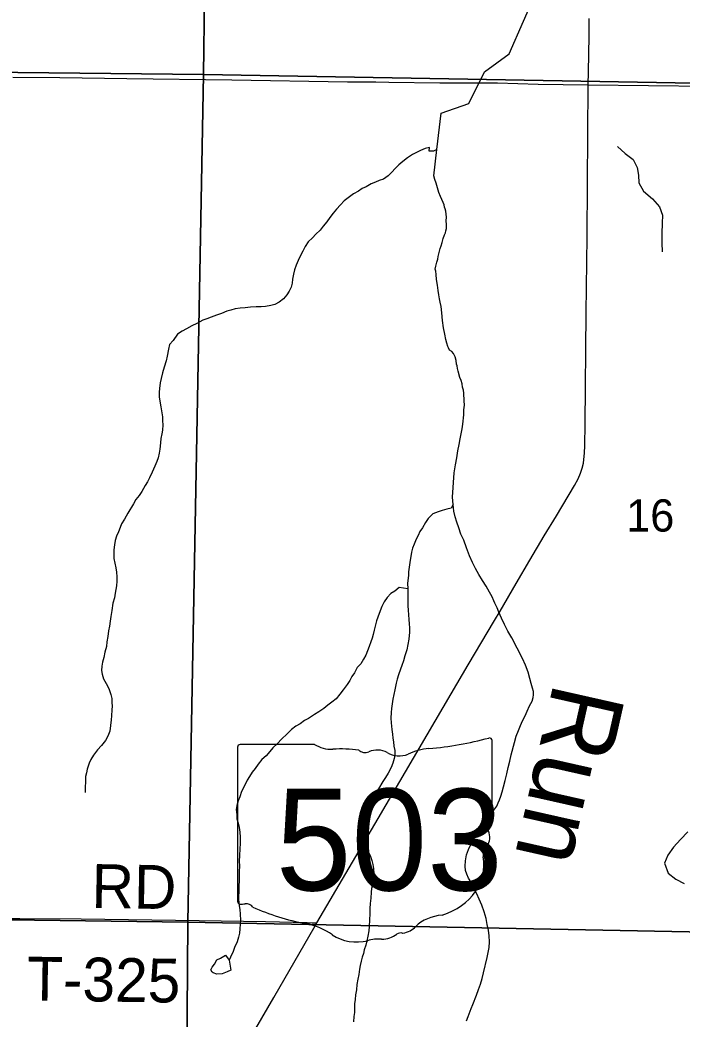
# Model space of a CAD drawing. Extents: x -8.8 to 41.4, y 0 to 34.6.
# Drawn here: x -3.661 to -2.803, y 15.304 to 16.599 of the extents above; entities that cross this region are included whole.
import ezdxf

# ---------------------------------------------------------------- set-up
doc = ezdxf.new("R2010")
doc.units = 0
for name, color, linetype in [('GM_X_City_Street', 7, 'Continuous'), ('GM_X_Corporation', 7, 'Continuous'), ('GM_X_County_Road', 7, 'Continuous'), ('GM_X_Minor_River', 7, 'Continuous'), ('GM_X_Minor_River_Text', 7, 'Continuous'), ('GM_X_Section_Text', 7, 'Continuous'), ('GM_X_State_Route', 7, 'Continuous'), ('GM_X_Township_Road', 7, 'Continuous'), ('GM_X_Township_Text', 7, 'Continuous'), ('GM_X_Unincorporated_Location', 7, 'Continuous')]:
    doc.layers.add(name, color=color, linetype=linetype)

msp = doc.modelspace()

# ---------------------------------------------------------------- linework, layer by layer
at = {"layer": 'GM_X_City_Street'}
for p, q in [((-3.0493, 15.5601), (-3.0493, 15.6648)), ((-3.3789, 15.6564), (-3.3789, 15.4563)), ((-3.2792, 15.6598), (-3.3757, 15.6598)), ((-3.0494, 15.5601), (-3.0493, 15.5601))]:
    msp.add_line(p, q, dxfattribs=at)
for centre, major_axis, start_param, end_param in [((-3.1667, 15.9326), (0.3495, 0), 4.814394, 5.042369), ((-3.053, 15.6652), (0.00367, 0), 6.141152, 7.989035), ((-3.3751, 15.6568), (0.00382, 0), 1.712693, 3.28349), ((-3.2562, 15.683), (0.037, 0), 4.042523, 4.731795), ((-3.2439, 15.5475), (0.133, 0), 1.404758, 1.657858), ((-3.2137, 15.6578), (0.0107, 0), 3.836095, 5.185415), ((-3.198, 15.6347), (0.0222, 0), 0.950623, 2.079405), ((-3.1694, 15.6664), (0.0267, 0), 4.081561, 5.145723), ((-3.1222, 15.5987), (0.0703, 0), 1.699011, 2.107814), ((-3.0533, 15.5597), (0.00393, 0), 5.05454, 6.418171), ((-3.0502, 15.5524), (0.00568, 0), 1.883978, 3.671073), ((-3.0863, 15.5392), (0.0341, 0), 5.934695, 6.695948), ((-3.0362, 15.5163), (0.0248, 0), 2.387724, 3.262537), ((-3.1472, 15.503), (0.0874, 0), 5.101752, 6.440018), ((-3.3751, 15.4558), (0.00385, 0), 3.00124, 4.508301), ((-3.3745, 15.4763), (0.0294, 0), 4.665946, 4.897461), ((-3.3685, 15.4447), (0.0106, 0), 0.519207, 1.627899), ((-3.2347, 15.6245), (0.2524, 0), 4.195997, 4.488961), ((-3.1103, 15.4001), (0.0479, 0), 1.647645, 2.488434), ((-3.3099, 15.3663), (0.079, 0), 0.823519, 1.323587), ((-3.1678, 15.4093), (0.00752, 0), 1.147584, 2.315152), ((-3.171, 15.4369), (0.0282, 0), 4.937069, 5.64225), ((-3.2245, 15.4437), (0.0501, 0), 4.026481, 4.996735), ((-3.1956, 15.3745), (0.0412, 0), 1.495662, 1.94098), ((-3.1919, 15.4287), (0.0267, 0), 4.691044, 5.507374)]:
    msp.add_ellipse(centre, major_axis=major_axis, ratio=0.8, start_param=start_param, end_param=end_param, dxfattribs=at)
at = {"layer": 'GM_X_Corporation'}
for points in [[(-3.4102, 17.5315), (-3.4233, 16.5283), (-4.4254, 16.539), (-4.4134, 17.5464)], [(-2.4162, 17.5144), (-2.421, 16.5107), (-3.4233, 16.5283), (-3.4102, 17.5315)], [(-4.4254, 16.539), (-3.4233, 16.5283), (-3.4436, 15.4293), (-4.4369, 15.4422)], [(-3.4233, 16.5283), (-2.421, 16.5107), (-2.4357, 15.4097), (-3.4436, 15.4293)], [(-4.4369, 15.4422), (-3.4436, 15.4293), (-3.4507, 14.4245), (-4.4383, 14.4395)], [(-3.4436, 15.4293), (-2.4357, 15.4097), (-2.4445, 14.411), (-3.4507, 14.4245)]]:
    msp.add_lwpolyline(points, close=True, dxfattribs=at)
at = {"layer": 'GM_X_County_Road'}
for points in [[(-3.6702, 16.5251), (-3.6094, 16.5244), (-3.5224, 16.5234), (-3.3864, 16.5217), (-3.2367, 16.5191), (-3.2, 16.5187), (-3.1832, 16.5184), (-3.1169, 16.5178), (-3.0424, 16.5174), (-2.9897, 16.516), (-2.9247, 16.5151)], [(-2.9247, 16.5151), (-2.6903, 16.5124), (-2.4218, 16.5093), (-2.1878, 16.5068), (-1.9834, 16.5044), (-1.8743, 16.5027)]]:
    msp.add_lwpolyline(points, dxfattribs=at)
at = {"layer": 'GM_X_Minor_River'}
for points in [[(-3.1207, 16.431), (-3.1153, 16.4782), (-3.0793, 16.4906), (-3.0589, 16.5317), (-3.027, 16.5553), (-2.9899, 16.6404)], [(-3.1359, 16.4324), (-3.1421, 16.4299), (-3.1471, 16.4274), (-3.1525, 16.4245), (-3.1587, 16.4205), (-3.1649, 16.4154), (-3.1699, 16.4113), (-3.184, 16.3969), (-3.1898, 16.3929), (-3.1956, 16.3908), (-3.2005, 16.3886), (-3.2059, 16.3865), (-3.2125, 16.3829), (-3.2175, 16.3808), (-3.2225, 16.3771), (-3.2287, 16.3735), (-3.2356, 16.3687), (-3.2407, 16.3647), (-3.2458, 16.3595), (-3.2509, 16.354), (-3.2552, 16.3488), (-3.2595, 16.3428), (-3.2635, 16.3372), (-3.2682, 16.3317), (-3.2721, 16.3265), (-3.2776, 16.3213), (-3.2819, 16.3165), (-3.2874, 16.3113), (-3.2913, 16.3053), (-3.2945, 16.2993), (-3.2977, 16.293), (-3.3006, 16.2874), (-3.303, 16.2813), (-3.3051, 16.2753), (-3.3064, 16.2697), (-3.3077, 16.2632), (-3.3082, 16.2579), (-3.3095, 16.2527), (-3.3123, 16.2474), (-3.3151, 16.2426), (-3.3194, 16.2377), (-3.3249, 16.2333), (-3.3306, 16.2301), (-3.336, 16.2287), (-3.3428, 16.2278), (-3.3486, 16.2272), (-3.355, 16.227), (-3.3622, 16.2268), (-3.3691, 16.2258), (-3.3755, 16.2256), (-3.382, 16.2247), (-3.3878, 16.2229), (-3.3931, 16.2216), (-3.4, 16.2187), (-3.4065, 16.2163), (-3.4134, 16.2138), (-3.4188, 16.2117), (-3.4242, 16.2099), (-3.4319, 16.2056), (-3.4384, 16.2027), (-3.445, 16.1987), (-3.4508, 16.1955), (-3.4566, 16.1915), (-3.4625, 16.1836), (-3.4672, 16.1781), (-3.4685, 16.1724), (-3.4703, 16.163), (-3.4716, 16.1573), (-3.4741, 16.149), (-3.4762, 16.1415), (-3.4779, 16.1343), (-3.4792, 16.1286), (-3.4802, 16.1214), (-3.4807, 16.1165), (-3.4805, 16.1104), (-3.4799, 16.1047), (-3.4786, 16.0975), (-3.4776, 16.0921), (-3.4763, 16.0845), (-3.4761, 16.0795), (-3.4758, 16.0742), (-3.4764, 16.0674), (-3.4773, 16.0625), (-3.4782, 16.0564), (-3.4788, 16.0507), (-3.4798, 16.0424), (-3.4807, 16.0375), (-3.482, 16.0314), (-3.4836, 16.0265), (-3.4861, 16.0205), (-3.4897, 16.0127), (-3.493, 16.0055), (-3.4958, 16.0003), (-3.4986, 15.9954), (-3.503, 15.9876), (-3.5065, 15.9824), (-3.5108, 15.9772), (-3.514, 15.9715), (-3.5212, 15.9596), (-3.5256, 15.9517), (-3.5292, 15.9458)], [(-3.1207, 16.431), (-3.125, 16.4291), (-3.1307, 16.4289), (-3.1302, 16.4338), (-3.1359, 16.4324)], [(-3.1246, 16.3972), (-3.1207, 16.431)], [(-2.887, 16.4349), (-2.877, 16.4259), (-2.8666, 16.4184), (-2.8612, 16.4079), (-2.8596, 16.398), (-2.8591, 16.3881), (-2.8533, 16.3773), (-2.8415, 16.3671), (-2.8323, 16.357), (-2.8284, 16.3462), (-2.8291, 16.3356), (-2.8295, 16.3223), (-2.8294, 16.3102), (-2.829, 16.2984)], [(-3.0058, 15.7625), (-3.0097, 15.7713), (-3.0236, 15.7979), (-3.0287, 15.8068), (-3.0333, 15.8153), (-3.0372, 15.8234), (-3.0404, 15.8311), (-3.0425, 15.8369), (-3.0443, 15.8404), (-3.0457, 15.8431), (-3.0472, 15.8461), (-3.0493, 15.8512), (-3.0525, 15.8573), (-3.0568, 15.8651), (-3.0619, 15.8724), (-3.0666, 15.8802), (-3.0709, 15.8879), (-3.0748, 15.8956), (-3.0787, 15.9045), (-3.0822, 15.9148), (-3.086, 15.9244), (-3.0896, 15.9325), (-3.0924, 15.9406), (-3.0948, 15.9479), (-3.0972, 15.9548), (-3.0989, 15.9624), (-3.0998, 15.9708), (-3.1006, 15.9803), (-3.0985, 16.0118), (-3.0967, 16.0224), (-3.0949, 16.0315), (-3.0935, 16.0405), (-3.0921, 16.0485), (-3.0907, 16.056), (-3.0881, 16.0689), (-3.0871, 16.0749), (-3.086, 16.087), (-3.0858, 16.0935), (-3.0852, 16.0995), (-3.0854, 16.1052), (-3.0859, 16.1151), (-3.0865, 16.1189), (-3.0875, 16.1232), (-3.0882, 16.1274), (-3.0895, 16.1316), (-3.0909, 16.1354), (-3.093, 16.1438), (-3.094, 16.1473), (-3.0946, 16.1507), (-3.0953, 16.153), (-3.096, 16.1576), (-3.0973, 16.1622), (-3.0991, 16.1668), (-3.1013, 16.1692), (-3.1043, 16.1708), (-3.1057, 16.1739), (-3.1068, 16.1758), (-3.1081, 16.18), (-3.1091, 16.185), (-3.1104, 16.1919), (-3.1121, 16.1999), (-3.1133, 16.2094), (-3.1145, 16.2193), (-3.1154, 16.2277), (-3.1164, 16.2331), (-3.1174, 16.2376), (-3.1183, 16.2426), (-3.1193, 16.2483), (-3.1202, 16.2552), (-3.1211, 16.2628), (-3.1217, 16.2689), (-3.1223, 16.2735), (-3.123, 16.2758), (-3.1221, 16.28), (-3.1208, 16.2852), (-3.1196, 16.289), (-3.1191, 16.2924), (-3.1165, 16.3026), (-3.1153, 16.3063), (-3.114, 16.3105), (-3.1127, 16.3158), (-3.1107, 16.3203), (-3.1098, 16.3233), (-3.109, 16.3259), (-3.1085, 16.3289), (-3.1084, 16.3339), (-3.1086, 16.3388), (-3.1084, 16.3434), (-3.1087, 16.3475), (-3.109, 16.3513), (-3.11, 16.3544), (-3.1107, 16.3563), (-3.1114, 16.3594), (-3.1128, 16.3625), (-3.1142, 16.3663), (-3.116, 16.3702), (-3.1181, 16.3756), (-3.1198, 16.3813), (-3.1219, 16.3874), (-3.1236, 16.3924), (-3.1246, 16.3972)], [(-3.0998, 15.9708), (-3.1021, 15.966), (-3.1079, 15.9646), (-3.114, 15.9629), (-3.119, 15.9615), (-3.1262, 15.9587), (-3.1321, 15.9528), (-3.1357, 15.9476), (-3.1396, 15.9408), (-3.1428, 15.936), (-3.1452, 15.9307), (-3.1477, 15.9259), (-3.1501, 15.9195), (-3.1522, 15.9142), (-3.1535, 15.9089), (-3.1557, 15.8957), (-3.1576, 15.8836), (-3.1577, 15.8786), (-3.1588, 15.8688), (-3.1586, 15.8616), (-3.1584, 15.8562), (-3.1585, 15.8513), (-3.1583, 15.846), (-3.1585, 15.8395), (-3.1579, 15.8338), (-3.1577, 15.8277), (-3.1571, 15.8216), (-3.1565, 15.8163), (-3.1562, 15.811), (-3.1564, 15.8053), (-3.157, 15.7962), (-3.1597, 15.7826), (-3.1622, 15.7747), (-3.1639, 15.7682), (-3.166, 15.7622), (-3.168, 15.7573), (-3.1705, 15.7498), (-3.1722, 15.7442), (-3.1734, 15.7392), (-3.1752, 15.7306), (-3.1778, 15.7185), (-3.1788, 15.7124), (-3.1797, 15.7064), (-3.1802, 15.7011), (-3.1804, 15.6938), (-3.1802, 15.6878), (-3.179, 15.679), (-3.1784, 15.6729), (-3.1777, 15.6679), (-3.1768, 15.663), (-3.1765, 15.6576), (-3.1752, 15.6519), (-3.1753, 15.6462), (-3.1762, 15.6413), (-3.1779, 15.6356), (-3.18, 15.63), (-3.184, 15.6225), (-3.1875, 15.6169), (-3.1907, 15.6117), (-3.1963, 15.602), (-3.1999, 15.596), (-3.2028, 15.5888), (-3.2044, 15.5839), (-3.2057, 15.5771), (-3.2071, 15.5707), (-3.208, 15.5658), (-3.21, 15.5594), (-3.2117, 15.5538), (-3.2134, 15.5485), (-3.2139, 15.5432), (-3.2145, 15.5371), (-3.2139, 15.5314), (-3.2125, 15.5264), (-3.2096, 15.521), (-3.2071, 15.5156), (-3.205, 15.5091), (-3.2036, 15.5041), (-3.2027, 15.4988), (-3.2025, 15.4916), (-3.203, 15.4851), (-3.204, 15.4779), (-3.2053, 15.473), (-3.2058, 15.4681)], [(-3.5292, 15.9458), (-3.5312, 15.9409), (-3.5333, 15.9352), (-3.5357, 15.9296), (-3.5374, 15.924), (-3.5383, 15.9187), (-3.5392, 15.9122), (-3.5394, 15.9069), (-3.5392, 15.9008), (-3.5382, 15.8947), (-3.5369, 15.8886), (-3.5359, 15.8829), (-3.5353, 15.8772), (-3.5355, 15.8715), (-3.536, 15.8654), (-3.5374, 15.8559), (-3.5384, 15.8499), (-3.5405, 15.8427), (-3.5419, 15.8336), (-3.5432, 15.8257), (-3.5442, 15.8196), (-3.5447, 15.8132), (-3.546, 15.8072), (-3.547, 15.7996), (-3.5483, 15.7928), (-3.5489, 15.7867), (-3.551, 15.7792), (-3.5523, 15.7724), (-3.554, 15.7663), (-3.5549, 15.7611), (-3.5551, 15.7557), (-3.5545, 15.7508), (-3.5527, 15.745), (-3.5491, 15.7389), (-3.5459, 15.7323), (-3.5431, 15.7246), (-3.5417, 15.7193), (-3.5418, 15.7143), (-3.5416, 15.7094), (-3.5417, 15.7044), (-3.5423, 15.6969), (-3.5429, 15.6916), (-3.5434, 15.6844), (-3.5444, 15.6768), (-3.5469, 15.6704), (-3.5501, 15.6648), (-3.5552, 15.6585), (-3.5606, 15.6529), (-3.5658, 15.6458), (-3.569, 15.6402), (-3.5714, 15.6354), (-3.5739, 15.6278), (-3.5748, 15.6229), (-3.5761, 15.618), (-3.5766, 15.5975)], [(-3.1586, 15.8616), (-3.1695, 15.8634), (-3.1754, 15.8586), (-3.1804, 15.8553), (-3.1851, 15.8502), (-3.189, 15.8446), (-3.1923, 15.8386), (-3.1943, 15.8329), (-3.1972, 15.8247), (-3.1989, 15.8198), (-3.2001, 15.8149), (-3.2022, 15.8077), (-3.2035, 15.8024), (-3.2048, 15.7975), (-3.2065, 15.7926), (-3.2085, 15.7866), (-3.2106, 15.781), (-3.213, 15.7757), (-3.2158, 15.7705), (-3.2194, 15.7641), (-3.2241, 15.7593), (-3.2277, 15.7526), (-3.2309, 15.7477), (-3.2337, 15.7425), (-3.2369, 15.7376), (-3.2424, 15.7306), (-3.2467, 15.725), (-3.2514, 15.719), (-3.2569, 15.7146), (-3.2619, 15.7106), (-3.2673, 15.7062), (-3.2739, 15.7022), (-3.2793, 15.6985), (-3.2871, 15.6934), (-3.2924, 15.6909), (-3.2979, 15.6865), (-3.3033, 15.6833), (-3.3091, 15.6789), (-3.3146, 15.6733), (-3.322, 15.6667), (-3.3274, 15.6608), (-3.3333, 15.6552), (-3.3372, 15.6504), (-3.3419, 15.6448), (-3.3474, 15.64), (-3.3525, 15.6341), (-3.3561, 15.6285), (-3.36, 15.6237), (-3.3636, 15.6181), (-3.3664, 15.6132), (-3.3704, 15.605)], [(-3.0824, 15.3014), (-3.0803, 15.307), (-3.0762, 15.3175), (-3.0742, 15.3224), (-3.0696, 15.3348), (-3.0668, 15.3419), (-3.0643, 15.349), (-3.0622, 15.3562), (-3.0604, 15.3634), (-3.0556, 15.3834), (-3.0543, 15.3898), (-3.053, 15.3966), (-3.0528, 15.4038), (-3.0529, 15.4114), (-3.0538, 15.419), (-3.0555, 15.4263), (-3.0571, 15.4339), (-3.0595, 15.4427), (-3.0627, 15.4512), (-3.0658, 15.4593), (-3.069, 15.4662), (-3.0719, 15.4716), (-3.0769, 15.4816), (-3.0798, 15.4863), (-3.0819, 15.4917), (-3.0836, 15.4963), (-3.0842, 15.502), (-3.0836, 15.5088), (-3.0823, 15.5167), (-3.0798, 15.5235), (-3.0773, 15.5291), (-3.0745, 15.5351), (-3.0713, 15.5407), (-3.0677, 15.5459), (-3.0641, 15.5515), (-3.0602, 15.5563), (-3.0563, 15.5604), (-3.0531, 15.5645), (-3.05, 15.5689), (-3.0468, 15.5745), (-3.0432, 15.5797), (-3.0412, 15.5842), (-3.0395, 15.588), (-3.0379, 15.5925), (-3.0362, 15.5981), (-3.0345, 15.6049), (-3.0323, 15.6128), (-3.0302, 15.6215), (-3.0284, 15.6298), (-3.0263, 15.6381), (-3.0245, 15.6464), (-3.0202, 15.6622), (-3.0181, 15.6705), (-3.0152, 15.678), (-3.0123, 15.6844), (-3.0099, 15.6904), (-3.0066, 15.6968), (-3.0038, 15.7028), (-3.0006, 15.7099), (-2.9974, 15.7159), (-2.9961, 15.7208), (-2.9956, 15.7242), (-2.9958, 15.7283), (-2.9968, 15.7329), (-2.9985, 15.7387), (-3.0002, 15.7452), (-3.0026, 15.7536), (-3.0058, 15.7625)], [(-3.3704, 15.605), (-3.374, 15.5986), (-3.3761, 15.5918), (-3.3781, 15.5866), (-3.3798, 15.5805), (-3.3807, 15.5752), (-3.3801, 15.5688), (-3.3799, 15.5634), (-3.3782, 15.5577), (-3.3768, 15.552), (-3.3762, 15.5459), (-3.3757, 15.5394), (-3.3755, 15.531), (-3.3761, 15.5246), (-3.3767, 15.5155), (-3.3769, 15.509), (-3.3767, 15.5018), (-3.3769, 15.495), (-3.3768, 15.4866), (-3.3776, 15.4585), (-3.3771, 15.4505), (-3.3761, 15.4455), (-3.3755, 15.4398), (-3.3753, 15.4318), (-3.3758, 15.4265), (-3.376, 15.4208), (-3.3765, 15.4152), (-3.3778, 15.4099), (-3.3795, 15.4038), (-3.3831, 15.3963), (-3.3848, 15.3911), (-3.388, 15.3839), (-3.39, 15.3801)], [(-2.7957, 15.5466), (-2.8051, 15.5366), (-2.8141, 15.5266), (-2.8216, 15.5162), (-2.8261, 15.5056), (-2.8211, 15.493), (-2.8111, 15.4851), (-2.8003, 15.4795)], [(-3.2058, 15.4681), (-3.2064, 15.4605), (-3.207, 15.4533), (-3.2075, 15.4469), (-3.2077, 15.44), (-3.208, 15.4321), (-3.2086, 15.4237), (-3.2091, 15.418), (-3.2101, 15.4112), (-3.2114, 15.4052), (-3.2127, 15.3995), (-3.2148, 15.3935), (-3.216, 15.3886), (-3.2177, 15.3837), (-3.219, 15.3788), (-3.2203, 15.3731), (-3.2212, 15.3682), (-3.2221, 15.3614), (-3.223, 15.3553), (-3.2244, 15.3485), (-3.225, 15.3417), (-3.2263, 15.3349), (-3.2268, 15.3288), (-3.2274, 15.3232), (-3.2277, 15.3122), (-3.2282, 15.3068), (-3.2288, 15.3)], [(-3.39, 15.3801), (-3.3877, 15.3671), (-3.3923, 15.365), (-3.3988, 15.3625), (-3.4057, 15.3619), (-3.4106, 15.3636), (-3.4121, 15.3644), (-3.4135, 15.3675), (-3.4119, 15.3709), (-3.4087, 15.375), (-3.4059, 15.3806), (-3.4013, 15.3827)], [(-3.4013, 15.3827), (-3.3945, 15.3864), (-3.39, 15.3801)]]:
    msp.add_lwpolyline(points, dxfattribs=at)
at = {"layer": 'GM_X_State_Route'}
msp.add_lwpolyline([(-3.399, 15.216), (-3.332, 15.3315), (-3.2784, 15.4246), (-3.2763, 15.4283), (-3.1967, 15.5638), (-3.1335, 15.6722), (-3.1024, 15.7253), (-3.0804, 15.7628), (-3.0461, 15.8204), (-3.0388, 15.8327), (-3.0179, 15.8686), (-3.0004, 15.8987), (-2.9819, 15.9303), (-2.966, 15.9563), (-2.9423, 15.9957), (-2.9379, 16.004), (-2.9347, 16.0115), (-2.9325, 16.018), (-2.931, 16.0245), (-2.9302, 16.0291), (-2.9294, 16.0372), (-2.929, 16.0472), (-2.9288, 16.0751), (-2.9274, 16.2193), (-2.9261, 16.318), (-2.9257, 16.387), (-2.9247, 16.5151), (-2.9244, 16.5319), (-2.9237, 16.578), (-2.9234, 16.601)], dxfattribs=at)
at = {"layer": 'GM_X_Township_Road'}
msp.add_lwpolyline([(-4.0439, 15.4382), (-4.0066, 15.4379), (-3.9166, 15.4363), (-3.8434, 15.4356), (-3.7621, 15.4344), (-3.7186, 15.4342), (-3.6609, 15.4342), (-3.5814, 15.4335), (-3.4286, 15.4315), (-3.343, 15.43), (-3.289, 15.429), (-3.2822, 15.4286), (-3.2763, 15.4283)], dxfattribs=at)

# ---------------------------------------------------------------- texts
at = {"layer": 'GM_X_City_Street'}
msp.add_text('503', height=0.13184, dxfattribs=at).set_placement((-3.3295, 15.4704))
at = {"layer": 'GM_X_Minor_River_Text'}
msp.add_text('Run', height=0.09466, rotation=257.2923, dxfattribs=at).set_placement((-2.9689, 15.7423))
at = {"layer": 'GM_X_Section_Text'}
for s, rotation, p in [('RD', 359.0128, (-3.5685, 15.4479)), ('T-325', 359.1574, (-3.652, 15.3278))]:
    msp.add_text(s, height=0.05682, rotation=rotation, dxfattribs=at).set_placement(p)
at = {"layer": 'GM_X_Township_Text'}
msp.add_text('16', height=0.04186, rotation=0, dxfattribs=at).set_placement((-2.8755, 15.9357))
at = {"layer": 'GM_X_Unincorporated_Location'}
for s in ['s', 'r']:
    msp.add_text(s, height=0.000189, dxfattribs=at).set_placement((-3.2178, 15.543))
msp.add_text('503', height=0.000189, rotation=0, dxfattribs=at).set_placement((-3.2847, 15.5292))

doc.saveas('drawing.dxf')
